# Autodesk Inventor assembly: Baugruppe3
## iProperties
Created: 2005-04
Part Number: Baugruppe3
Cost Center: 0,1 kg
Document SubType Name: Assembly
Designer: Nützel
Authority: 7576,64 mm^3
Manufacturer: Standard
Standards Organization: Custom
Author: Nützel
SaveDate: 2005-04-24
SaveTime: 14:19
TotalMass: 0,1 kg
TotalVolume: 7576,64 mm^3
